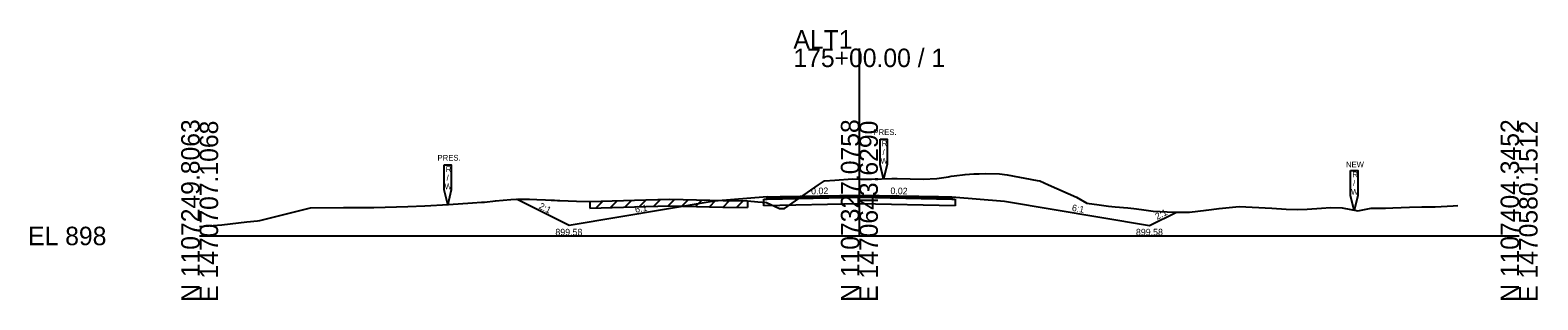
# Model space of a CAD drawing. Extents: x -26 to 2203, y -10 to 19568.
# Drawn here: x 974.3 to 1202.8, y 16990.3 to 17031.2 of the extents above; entities that cross this region are included whole.
import ezdxf

# ---------------------------------------------------------------- set-up
doc = ezdxf.new("R2010")
doc.units = 0
for name, color, linetype in [('RD_GPK_XS_Cell', 7, 'Continuous'), ('RD_XS_Base', 7, 'Continuous'), ('RD_XS_ExGround', 7, 'Continuous'), ('RD_XS_ExPaveRet', 7, 'Continuous'), ('RD_XS_ExRW', 7, 'Continuous'), ('RD_XS_Greenside', 7, 'Continuous'), ('RD_XS_NewRW', 7, 'Continuous'), ('RD_XS_Pave', 7, 'Continuous'), ('RD_XS_TieSlope', 7, 'Continuous'), ('RD_XS_TX_Slope', 7, 'Continuous')]:
    doc.layers.add(name, color=color, linetype=linetype)

msp = doc.modelspace()

# ---------------------------------------------------------------- linework, layer by layer
at = {"layer": 'RD_GPK_XS_Cell'}
for p, q in [((1100, 17000), (1100, 17028.41)), ((1000, 17000), (1100, 17000)), ((1100, 17000), (1200, 17000))]:
    msp.add_line(p, q, dxfattribs=at)
at = {"layer": 'RD_XS_Base'}
for points in [[(1085.5, 17005.59), (1086, 17005.6), (1100, 17005.88), (1114, 17005.6), (1114.5, 17005.59)], [(1085.5, 17004.59), (1085.5, 17005.59)], [(1114.5, 17005.59), (1114.5, 17004.59)], [(1114.5, 17004.59), (1100, 17004.88), (1085.5, 17004.59)]]:
    msp.add_lwpolyline(points, dxfattribs=at)
at = {"layer": 'RD_XS_ExGround'}
msp.add_lwpolyline([(1000, 17001.41), (1001.4, 17001.53), (1003.35, 17001.7), (1007.13, 17002.15), (1008.79, 17002.3), (1009.11, 17002.35), (1015.98, 17004.05), (1016.4, 17004.16), (1016.81, 17004.28), (1021.81, 17004.31), (1023.16, 17004.33), (1026.39, 17004.31), (1031.54, 17004.49), (1034.11, 17004.57), (1037.7, 17004.79), (1041.37, 17005.01), (1042.71, 17005.1), (1043.18, 17005.13), (1044.83, 17005.34), (1046, 17005.42), (1047.17, 17005.55), (1048.28, 17005.59), (1049.33, 17005.57), (1050.02, 17005.57), (1051.1, 17005.55), (1052.43, 17005.49), (1053.26, 17005.44), (1053.79, 17005.43), (1054.22, 17005.39), (1054.58, 17005.37), (1057.12, 17005.28), (1059.14, 17005.22), (1067.62, 17005.48), (1071.25, 17005.58), (1079.34, 17005.39), (1083.06, 17005.33), (1084.61, 17005.18), (1085.93, 17005.07), (1087.89, 17004.16), (1088.21, 17004.16), (1088.64, 17004.16), (1093.82, 17007.77), (1094.73, 17008.37), (1096.27, 17008.48), (1098.97, 17008.65), (1100.2, 17008.62), (1101.84, 17008.62), (1104.93, 17008.71), (1105.73, 17008.73), (1109.66, 17008.59), (1111.76, 17008.71), (1113.49, 17008.99), (1113.89, 17009.05), (1114.38, 17009.1), (1116.02, 17009.32), (1117.37, 17009.4), (1118.16, 17009.44), (1119.11, 17009.47), (1121.26, 17009.4), (1122.42, 17009.26), (1126.96, 17008.43), (1127.35, 17008.36), (1128.69, 17007.73), (1132.93, 17005.86), (1134.5, 17004.96), (1136.35, 17004.71), (1137.78, 17004.5), (1138.78, 17004.4), (1140.67, 17004.26), (1141.6, 17004.17), (1142.74, 17004), (1144.55, 17003.76), (1147.69, 17003.63), (1150.04, 17003.59), (1152.56, 17003.91), (1154.53, 17004.16), (1157.57, 17004.45), (1162.5, 17004.2), (1164.71, 17004.08), (1166.37, 17004.03), (1167.85, 17004.06), (1170.03, 17004.22), (1171.42, 17004.32), (1173.18, 17004.26), (1175.53, 17003.81), (1177.58, 17004.19), (1179.76, 17004.2), (1180.87, 17004.24), (1183.38, 17004.38), (1185.27, 17004.44), (1187.26, 17004.41), (1190, 17004.55), (1190.71, 17004.61)], dxfattribs=at)
at = {"layer": 'RD_XS_ExPaveRet'}
for p, q in [((1059.14, 17005.22), (1059.14, 17004.22)), ((1060.09, 17004.25), (1061.12, 17005.28)), ((1062.28, 17004.31), (1063.31, 17005.34)), ((1064.47, 17004.38), (1065.5, 17005.41)), ((1066.66, 17004.45), (1067.69, 17005.48)), ((1068.84, 17004.51), (1069.87, 17005.54)), ((1071.02, 17004.57), (1072.01, 17005.56)), ((1073.11, 17004.54), (1074.09, 17005.51)), ((1075.18, 17004.49), (1076.16, 17005.46)), ((1077.26, 17004.44), (1078.23, 17005.42)), ((1079.33, 17004.39), (1080.31, 17005.37)), ((1081.42, 17004.36), (1082.4, 17005.34)), ((1083.06, 17005.33), (1083.06, 17004.33))]:
    msp.add_line(p, q, dxfattribs=at)
msp.add_lwpolyline([(1059.14, 17004.22), (1067.65, 17004.48), (1071.25, 17004.58), (1079.32, 17004.39), (1083.06, 17004.33)], dxfattribs=at)
at = {"layer": 'RD_XS_ExRW'}
for points in [[(1103.13, 17014.69), (1104.22, 17014.69), (1104.22, 17010.86), (1103.68, 17008.67), (1103.13, 17010.86)], [(1037.05, 17010.8), (1038.14, 17010.8), (1038.14, 17006.97), (1037.6, 17004.78), (1037.05, 17006.97)]]:
    msp.add_lwpolyline(points, close=True, dxfattribs=at)
at = {"layer": 'RD_XS_Greenside'}
for points in [[(1078, 17005.25), (1056, 17001.58)], [(1086, 17005.92), (1078, 17005.25)], [(1114, 17005.92), (1122, 17005.25)], [(1122, 17005.25), (1144, 17001.58)]]:
    msp.add_lwpolyline(points, dxfattribs=at)
at = {"layer": 'RD_XS_NewRW'}
msp.add_lwpolyline([(1174.45, 17009.92), (1175.55, 17009.92), (1175.55, 17006.1), (1175, 17003.91), (1174.45, 17006.1)], close=True, dxfattribs=at)
at = {"layer": 'RD_XS_Pave'}
for points in [[(1086, 17005.92), (1088, 17005.96), (1100, 17006.2), (1112, 17005.96), (1114, 17005.92)], [(1086, 17005.76), (1100, 17006.04), (1114, 17005.76)], [(1114, 17005.76), (1100, 17006.04), (1086, 17005.76)], [(1086, 17005.76), (1086, 17005.92)], [(1114, 17005.6), (1100, 17005.88), (1086, 17005.6)], [(1086, 17005.6), (1086, 17005.76)], [(1114, 17005.92), (1114, 17005.76)], [(1114, 17005.76), (1114, 17005.6)]]:
    msp.add_lwpolyline(points, dxfattribs=at)
at = {"layer": 'RD_XS_TieSlope'}
for points in [[(1056, 17001.58), (1048.01, 17005.58)], [(1144, 17001.58), (1148.09, 17003.63)]]:
    msp.add_lwpolyline(points, dxfattribs=at)

# ---------------------------------------------------------------- texts
at = {"layer": 'RD_GPK_XS_Cell'}
for s, p in [('ALT1', (1090, 17028.41)), ('175+00.00 / 1', (1090, 17025.61)), ('EL 898', (974, 16998.6))]:
    msp.add_text(s, height=2.8, dxfattribs=at).set_placement(p)
for s, p in [('N 1107249.8063', (1000, 16990)), ('E 1470707.1068', (1002.8, 16990)), ('N 1107327.0758', (1100, 16990)), ('E 1470643.6290', (1102.8, 16990)), ('N 1107404.3452', (1200, 16990)), ('E 1470580.1512', (1202.8, 16990))]:
    msp.add_text(s, height=2.8, rotation=90, dxfattribs=at).set_placement(p)
at = {"layer": 'RD_XS_ExRW'}
for s, p in [('PRES.', (1102.13, 17015.31)), ('R', (1103.39, 17013.6)), ('PRES.', (1036.05, 17011.42)), ('/', (1103.51, 17012.28)), ('R', (1037.31, 17009.7)), ('W', (1103.2, 17010.97)), ('W', (1037.12, 17007.08)), ('/', (1037.43, 17008.39))]:
    msp.add_text(s, height=0.875, dxfattribs=at).set_placement(p)
at = {"layer": 'RD_XS_NewRW'}
for s, p in [('NEW', (1173.75, 17010.41)), ('R', (1174.71, 17008.89)), ('/', (1174.83, 17007.57)), ('W', (1174.53, 17006.26))]:
    msp.add_text(s, height=0.875, dxfattribs=at).set_placement(p)
at = {"layer": 'RD_XS_TX_Slope'}
for s, rotation, p in [('0.02', 1.1458, (1092.69, 17006.3)), ('0.02', 358.8542, (1104.7, 17006.35)), ('2:1', 333.4349, (1051.31, 17004.2)), ('6:1', 9.4642, (1066.07, 17003.51)), ('6:1', 350.5358, (1132.16, 17003.81)), ('2:1', 26.5651, (1145.13, 17002.43))]:
    msp.add_text(s, height=1, rotation=rotation, dxfattribs=at).set_placement(p)
for p in [(1053.92, 17000.08), (1141.92, 17000.08)]:
    msp.add_text('899.58', height=1, dxfattribs=at).set_placement(p)

doc.saveas('drawing.dxf')
